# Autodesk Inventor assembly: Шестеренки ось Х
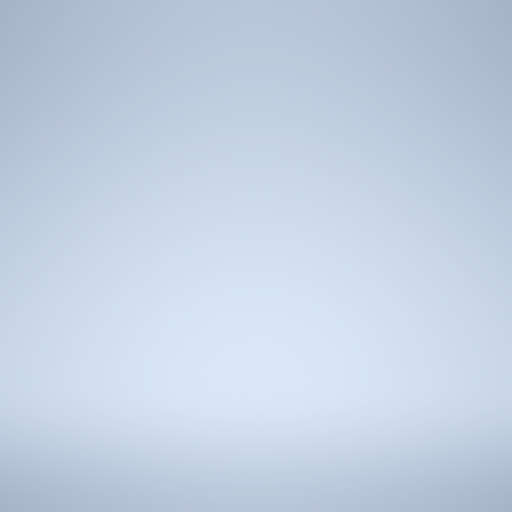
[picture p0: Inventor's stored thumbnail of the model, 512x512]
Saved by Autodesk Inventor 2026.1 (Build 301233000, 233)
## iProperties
Created: 2026-02
Part Number: Шестеренки ось Х
Document SubType Name: Assembly
Designer: Yury Melnikov
Author: Yury Melnikov
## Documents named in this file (1)
- C:\Users\user\Documents\Проекты\ВсОШ_РОБО\Робот V2\Шестеренки ось Х.iam
